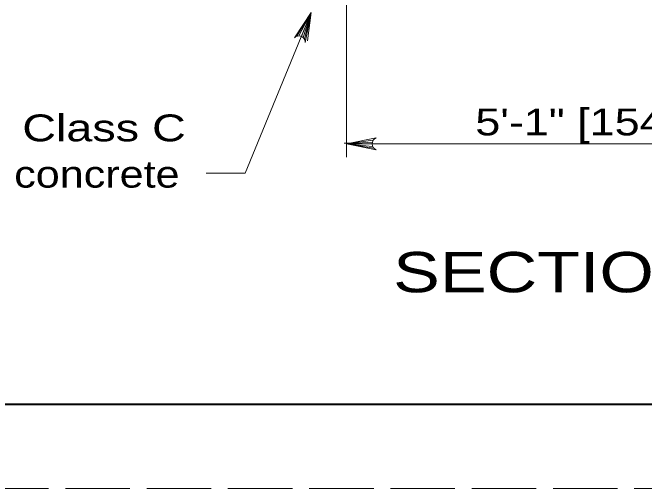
# Model space of a CAD drawing. Extents: x 750.7 to 784.7, y 860.1 to 882.1.
# Drawn here: x 760.016 to 763.779, y 860.118 to 862.952 of the extents above; entities that cross this region are included whole.
import ezdxf

# ---------------------------------------------------------------- set-up
doc = ezdxf.new("R2010")
doc.units = 0
doc.header["$LTSCALE"] = 0.064
doc.linetypes.add('LONG_DASHED', pattern=[7.5, 6, -1.5])
doc.layers.add('1', color=7, linetype='Continuous', lineweight=13)

msp = doc.modelspace()

# ---------------------------------------------------------------- linework, layer by layer
at = {"layer": '1'}
for p, q in [((762.00408, 863.15042), (762.00408, 862.09025)), ((761.70975, 862.81167), (761.79508, 862.95183)), ((761.72175, 862.81333), (761.79508, 862.95183)), ((761.73608, 862.81042), (761.79508, 862.95183)), ((761.74592, 862.8045), (761.79508, 862.95183)), ((761.75408, 862.79517), (761.79508, 862.95183)), ((761.79508, 862.95183), (761.77167, 862.78392)), ((761.99017, 862.17433), (762.08517, 862.17433)), ((762.16442, 862.19242), (762.00408, 862.17)), ((762.159, 862.18133), (762.00408, 862.17)), ((764.23992, 862.17), (762.00408, 862.17)), ((762.15733, 862.17), (762.00408, 862.17)), ((762.16017, 862.15558), (762.00408, 862.17)), ((762.16633, 862.14517), (762.00408, 862.17))]:
    msp.add_line(p, q, dxfattribs=at)
at = {"layer": '1', "linetype": 'LONG_DASHED'}
msp.add_lwpolyline([(750.65083, 860.11842), (784.65083, 860.11842), (784.65083, 882.11842), (750.65083, 882.11842)], close=True, dxfattribs=at)
at = {"layer": '1', "lineweight": 25}
msp.add_lwpolyline([(784.15083, 860.61842), (752.65083, 860.61842), (752.65083, 881.61842)], dxfattribs=at)
at = {"layer": '1', "lineweight": 40}
msp.add_lwpolyline([(752.65083, 881.61842), (784.15083, 881.61842), (784.15083, 860.61842), (752.65083, 860.61842)], close=True, dxfattribs=at)
at = {"layer": '1'}
for points in [[(761.79508, 862.95183), (761.4015, 861.99483), (761.16833, 861.99483)], [(761.69417, 862.802), (761.79508, 862.95183), (761.75958, 862.77483)], [(762.18117, 862.13458), (762.00408, 862.17), (762.18117, 862.20542)]]:
    msp.add_lwpolyline(points, dxfattribs=at)
for centre, radius, start, end in [((761.72144, 862.77519), 0.03822, 359.44675, 135.27288), ((762.00018, 862.17825), 0.00394, 270, 0), ((762.19549, 862.17002), 0.03822, 112.08782, 247.91395)]:
    msp.add_arc(centre, radius, start, end, dxfattribs=at)

# ---------------------------------------------------------------- texts
for s, height, width, p in [('5\'-1" [1545] min.', 0.16, 1.25, (762.77208, 862.22075)), ('Class C', 0.16, 1.3, (760.074, 862.18533)), ('concrete', 0.16, 1.2, (760.02583, 861.90967)), ('SECTION B-B', 0.24, 1.3, (762.28242, 861.28642))]:
    msp.add_text(s, height=height, dxfattribs=dict(at, width=width)).set_placement(p)

doc.saveas('drawing.dxf')
